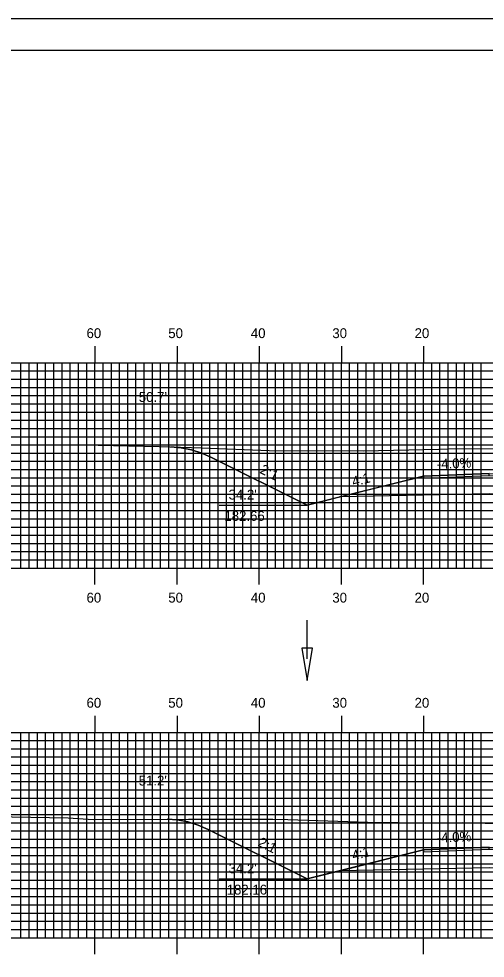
# Model space of a CAD drawing. Extents: x 1797601 to 1797944, y 442591 to 442811.
# Drawn here: x 1797697.2 to 1797753.9, y 442696.2 to 442810.5 of the extents above; entities that cross this region are included whole.
import ezdxf

# ---------------------------------------------------------------- set-up
doc = ezdxf.new("R2010")
doc.units = 0
for name, color, linetype in [('ANNOTATION', 7, 'Continuous'), ('BORDER', 7, 'Continuous'), ('D_Drainage_Ditch_Line', 7, 'Continuous'), ('D_Roadway_Centerline', 7, 'Continuous'), ('D_Roadway_Edge_Shoulder', 7, 'Continuous'), ('D_Roadway_SlopeLines', 7, 'Continuous'), ('D_Roadway_SubGrade', 7, 'Continuous'), ('D_Text_Standard', 7, 'Continuous'), ('H_V ANNOTATION', 7, 'Continuous'), ('MAJOR', 7, 'Continuous'), ('MINOR', 7, 'Continuous'), ('PDRAIN', 7, 'Continuous'), ('PLOT BOUNDARY', 7, 'Continuous'), ('S_Roadway_Centerline', 7, 'Continuous')]:
    doc.layers.add(name, color=color, linetype=linetype)

msp = doc.modelspace()

# ---------------------------------------------------------------- linework, layer by layer
at = {"layer": 'BORDER'}
msp.add_lwpolyline([(1797616.84, 442596.67), (1797936.84, 442596.67), (1797936.84, 442806.67), (1797616.84, 442806.67)], close=True, dxfattribs=at)
at = {"layer": 'D_Drainage_Ditch_Line'}
msp.add_line((1797732.27, 442732.63), (1797732.27, 442737.33), dxfattribs=at)
msp.add_lwpolyline([(1797732.93, 442733.94), (1797731.61, 442733.94), (1797732.27, 442730)], close=True, dxfattribs=at)
at = {"layer": 'D_Roadway_Centerline'}
for points in [[(1797715.7, 442758.42), (1797716.95, 442758.32), (1797718.2, 442758.06), (1797719.45, 442757.66), (1797720.7, 442757.11), (1797732.27, 442751.33), (1797736.27, 442752.33), (1797746.44, 442754.87), (1797754.44, 442755.19), (1797766.44, 442754.95), (1797778.44, 442754.71), (1797786.44, 442754.39), (1797796.62, 442751.85), (1797800.62, 442750.85), (1797811.54, 442756.31), (1797812.79, 442756.85), (1797814.04, 442757.24), (1797815.29, 442757.48), (1797816.54, 442757.55)], [(1797715.24, 442713.09), (1797716.49, 442713.01), (1797717.74, 442712.78), (1797718.99, 442712.39), (1797720.24, 442711.84), (1797732.27, 442705.83), (1797736.27, 442706.83), (1797746.44, 442709.37), (1797754.44, 442709.69), (1797766.44, 442709.45), (1797778.44, 442709.21), (1797786.44, 442708.89), (1797796.62, 442706.35), (1797800.62, 442705.35), (1797811.55, 442710.81), (1797812.8, 442711.35), (1797814.05, 442711.73), (1797815.3, 442711.95), (1797816.55, 442712.01)]]:
    msp.add_lwpolyline(points, dxfattribs=at)
at = {"layer": 'D_Roadway_Edge_Shoulder'}
for points in [[(1797754.44, 442755.19), (1797746.44, 442754.87), (1797746.44, 442754.62), (1797754.44, 442754.94)], [(1797754.44, 442709.69), (1797746.44, 442709.37), (1797746.44, 442709.12), (1797754.44, 442709.44)]]:
    msp.add_lwpolyline(points, close=True, dxfattribs=at)
at = {"layer": 'D_Roadway_SlopeLines'}
for points in [[(1797732.27, 442751.33), (1797720.7, 442757.11), (1797719.45, 442757.66), (1797718.2, 442758.06), (1797716.95, 442758.32), (1797715.7, 442758.42)], [(1797746.44, 442754.87), (1797732.27, 442751.33)], [(1797732.27, 442705.83), (1797720.24, 442711.84), (1797718.99, 442712.39), (1797717.74, 442712.78), (1797716.49, 442713.01), (1797715.24, 442713.09)], [(1797746.44, 442709.37), (1797732.27, 442705.83)]]:
    msp.add_lwpolyline(points, dxfattribs=at)
at = {"layer": 'D_Roadway_SubGrade'}
for points in [[(1797754.44, 442752.69), (1797736.27, 442752.33), (1797746.44, 442754.87), (1797746.44, 442754.62), (1797754.44, 442754.94), (1797766.44, 442754.7), (1797778.44, 442754.46), (1797786.44, 442754.14), (1797786.44, 442754.39), (1797796.62, 442751.85), (1797778.44, 442752.21), (1797766.44, 442752.45)], [(1797754.44, 442707.19), (1797736.27, 442706.83), (1797746.44, 442709.37), (1797746.44, 442709.12), (1797754.44, 442709.44), (1797766.44, 442709.2), (1797778.44, 442708.96), (1797786.44, 442708.64), (1797786.44, 442708.89), (1797796.62, 442706.35), (1797778.44, 442706.71), (1797766.44, 442706.95)]]:
    msp.add_lwpolyline(points, close=True, dxfattribs=at)
at = {"layer": 'MAJOR'}
for p, q in [((1797706.44, 442770.67), (1797706.44, 442768.67)), ((1797716.44, 442770.67), (1797716.44, 442768.67)), ((1797726.44, 442770.67), (1797726.44, 442768.67)), ((1797736.44, 442770.67), (1797736.44, 442768.67)), ((1797746.44, 442770.67), (1797746.44, 442768.67)), ((1797626.44, 442768.67), (1797906.44, 442768.67)), ((1797626.44, 442768.67), (1797906.44, 442768.67)), ((1797706.44, 442743.67), (1797706.44, 442768.67)), ((1797716.44, 442743.67), (1797716.44, 442768.67)), ((1797726.44, 442743.67), (1797726.44, 442768.67)), ((1797736.44, 442743.67), (1797736.44, 442768.67)), ((1797746.44, 442743.67), (1797746.44, 442768.67)), ((1797626.44, 442763.67), (1797906.44, 442763.67)), ((1797626.44, 442758.67), (1797906.44, 442758.67)), ((1797626.44, 442753.67), (1797906.44, 442753.67)), ((1797626.44, 442748.67), (1797906.44, 442748.67)), ((1797626.44, 442743.67), (1797906.44, 442743.67)), ((1797626.44, 442743.67), (1797906.44, 442743.67)), ((1797706.44, 442741.66), (1797706.44, 442743.67)), ((1797716.44, 442741.66), (1797716.44, 442743.67)), ((1797726.44, 442741.66), (1797726.44, 442743.67)), ((1797736.44, 442741.66), (1797736.44, 442743.67)), ((1797746.44, 442741.66), (1797746.44, 442743.67)), ((1797706.44, 442725.67), (1797706.44, 442723.67)), ((1797716.44, 442725.67), (1797716.44, 442723.67)), ((1797726.44, 442725.67), (1797726.44, 442723.67)), ((1797736.44, 442725.67), (1797736.44, 442723.67)), ((1797746.44, 442725.67), (1797746.44, 442723.67)), ((1797626.44, 442723.67), (1797906.44, 442723.67)), ((1797626.44, 442723.67), (1797906.44, 442723.67)), ((1797706.44, 442698.67), (1797706.44, 442723.67)), ((1797716.44, 442698.67), (1797716.44, 442723.67)), ((1797726.44, 442698.67), (1797726.44, 442723.67)), ((1797736.44, 442698.67), (1797736.44, 442723.67)), ((1797746.44, 442698.67), (1797746.44, 442723.67)), ((1797626.44, 442718.67), (1797906.44, 442718.67)), ((1797626.44, 442713.67), (1797906.44, 442713.67)), ((1797626.44, 442708.67), (1797906.44, 442708.67)), ((1797626.44, 442703.67), (1797906.44, 442703.67)), ((1797626.44, 442698.67), (1797906.44, 442698.67)), ((1797626.44, 442698.67), (1797906.44, 442698.67)), ((1797706.44, 442696.66), (1797706.44, 442698.67)), ((1797716.44, 442696.66), (1797716.44, 442698.67)), ((1797726.44, 442696.66), (1797726.44, 442698.67)), ((1797736.44, 442696.66), (1797736.44, 442698.67)), ((1797746.44, 442696.66), (1797746.44, 442698.67))]:
    msp.add_line(p, q, dxfattribs=at)
at = {"layer": 'MINOR'}
for p, q in [((1797626.44, 442767.67), (1797906.44, 442767.67)), ((1797697.44, 442743.67), (1797697.44, 442768.67)), ((1797698.44, 442743.67), (1797698.44, 442768.67)), ((1797699.44, 442743.67), (1797699.44, 442768.67)), ((1797700.44, 442743.67), (1797700.44, 442768.67)), ((1797701.44, 442743.67), (1797701.44, 442768.67)), ((1797702.44, 442743.67), (1797702.44, 442768.67)), ((1797703.44, 442743.67), (1797703.44, 442768.67)), ((1797704.44, 442743.67), (1797704.44, 442768.67)), ((1797705.44, 442743.67), (1797705.44, 442768.67)), ((1797707.44, 442743.67), (1797707.44, 442768.67)), ((1797708.44, 442743.67), (1797708.44, 442768.67)), ((1797709.44, 442743.67), (1797709.44, 442768.67)), ((1797710.44, 442743.67), (1797710.44, 442768.67)), ((1797711.44, 442743.67), (1797711.44, 442768.67)), ((1797712.44, 442743.67), (1797712.44, 442768.67)), ((1797713.44, 442743.67), (1797713.44, 442768.67)), ((1797714.44, 442743.67), (1797714.44, 442768.67)), ((1797715.44, 442743.67), (1797715.44, 442768.67)), ((1797717.44, 442743.67), (1797717.44, 442768.67)), ((1797718.44, 442743.67), (1797718.44, 442768.67)), ((1797719.44, 442743.67), (1797719.44, 442768.67)), ((1797720.44, 442743.67), (1797720.44, 442768.67)), ((1797721.44, 442743.67), (1797721.44, 442768.67)), ((1797722.44, 442743.67), (1797722.44, 442768.67)), ((1797723.44, 442743.67), (1797723.44, 442768.67)), ((1797724.44, 442743.67), (1797724.44, 442768.67)), ((1797725.44, 442743.67), (1797725.44, 442768.67)), ((1797727.44, 442743.67), (1797727.44, 442768.67)), ((1797728.44, 442743.67), (1797728.44, 442768.67)), ((1797729.44, 442743.67), (1797729.44, 442768.67)), ((1797730.44, 442743.67), (1797730.44, 442768.67)), ((1797731.44, 442743.67), (1797731.44, 442768.67)), ((1797732.44, 442743.67), (1797732.44, 442768.67)), ((1797733.44, 442743.67), (1797733.44, 442768.67)), ((1797734.44, 442743.67), (1797734.44, 442768.67)), ((1797735.44, 442743.67), (1797735.44, 442768.67)), ((1797737.44, 442743.67), (1797737.44, 442768.67)), ((1797738.44, 442743.67), (1797738.44, 442768.67)), ((1797739.44, 442743.67), (1797739.44, 442768.67)), ((1797740.44, 442743.67), (1797740.44, 442768.67)), ((1797741.44, 442743.67), (1797741.44, 442768.67)), ((1797742.44, 442743.67), (1797742.44, 442768.67)), ((1797743.44, 442743.67), (1797743.44, 442768.67)), ((1797744.44, 442743.67), (1797744.44, 442768.67)), ((1797745.44, 442743.67), (1797745.44, 442768.67)), ((1797747.44, 442743.67), (1797747.44, 442768.67)), ((1797748.44, 442743.67), (1797748.44, 442768.67)), ((1797749.44, 442743.67), (1797749.44, 442768.67)), ((1797750.44, 442743.67), (1797750.44, 442768.67)), ((1797751.44, 442743.67), (1797751.44, 442768.67)), ((1797752.44, 442743.67), (1797752.44, 442768.67)), ((1797753.44, 442743.67), (1797753.44, 442768.67)), ((1797626.44, 442766.67), (1797906.44, 442766.67)), ((1797626.44, 442765.67), (1797906.44, 442765.67)), ((1797626.44, 442764.67), (1797906.44, 442764.67)), ((1797626.44, 442762.67), (1797906.44, 442762.67)), ((1797626.44, 442761.67), (1797906.44, 442761.67)), ((1797626.44, 442760.67), (1797906.44, 442760.67)), ((1797626.44, 442759.67), (1797906.44, 442759.67)), ((1797626.44, 442757.67), (1797906.44, 442757.67)), ((1797626.44, 442756.67), (1797906.44, 442756.67)), ((1797626.44, 442755.67), (1797906.44, 442755.67)), ((1797626.44, 442754.67), (1797906.44, 442754.67)), ((1797626.44, 442752.67), (1797906.44, 442752.67)), ((1797626.44, 442751.67), (1797906.44, 442751.67)), ((1797626.44, 442750.67), (1797906.44, 442750.67)), ((1797626.44, 442749.67), (1797906.44, 442749.67)), ((1797626.44, 442747.67), (1797906.44, 442747.67)), ((1797626.44, 442746.67), (1797906.44, 442746.67)), ((1797626.44, 442745.67), (1797906.44, 442745.67)), ((1797626.44, 442744.67), (1797906.44, 442744.67)), ((1797697.44, 442698.67), (1797697.44, 442723.67)), ((1797698.44, 442698.67), (1797698.44, 442723.67)), ((1797699.44, 442698.67), (1797699.44, 442723.67)), ((1797700.44, 442698.67), (1797700.44, 442723.67)), ((1797701.44, 442698.67), (1797701.44, 442723.67)), ((1797702.44, 442698.67), (1797702.44, 442723.67)), ((1797703.44, 442698.67), (1797703.44, 442723.67)), ((1797704.44, 442698.67), (1797704.44, 442723.67)), ((1797705.44, 442698.67), (1797705.44, 442723.67)), ((1797707.44, 442698.67), (1797707.44, 442723.67)), ((1797708.44, 442698.67), (1797708.44, 442723.67)), ((1797709.44, 442698.67), (1797709.44, 442723.67)), ((1797710.44, 442698.67), (1797710.44, 442723.67)), ((1797711.44, 442698.67), (1797711.44, 442723.67)), ((1797712.44, 442698.67), (1797712.44, 442723.67)), ((1797713.44, 442698.67), (1797713.44, 442723.67)), ((1797714.44, 442698.67), (1797714.44, 442723.67)), ((1797715.44, 442698.67), (1797715.44, 442723.67)), ((1797717.44, 442698.67), (1797717.44, 442723.67)), ((1797718.44, 442698.67), (1797718.44, 442723.67)), ((1797719.44, 442698.67), (1797719.44, 442723.67)), ((1797720.44, 442698.67), (1797720.44, 442723.67)), ((1797721.44, 442698.67), (1797721.44, 442723.67)), ((1797722.44, 442698.67), (1797722.44, 442723.67)), ((1797723.44, 442698.67), (1797723.44, 442723.67)), ((1797724.44, 442698.67), (1797724.44, 442723.67)), ((1797725.44, 442698.67), (1797725.44, 442723.67)), ((1797727.44, 442698.67), (1797727.44, 442723.67)), ((1797728.44, 442698.67), (1797728.44, 442723.67)), ((1797729.44, 442698.67), (1797729.44, 442723.67)), ((1797730.44, 442698.67), (1797730.44, 442723.67)), ((1797731.44, 442698.67), (1797731.44, 442723.67)), ((1797732.44, 442698.67), (1797732.44, 442723.67)), ((1797733.44, 442698.67), (1797733.44, 442723.67)), ((1797734.44, 442698.67), (1797734.44, 442723.67)), ((1797735.44, 442698.67), (1797735.44, 442723.67)), ((1797737.44, 442698.67), (1797737.44, 442723.67)), ((1797738.44, 442698.67), (1797738.44, 442723.67)), ((1797739.44, 442698.67), (1797739.44, 442723.67)), ((1797740.44, 442698.67), (1797740.44, 442723.67)), ((1797741.44, 442698.67), (1797741.44, 442723.67)), ((1797742.44, 442698.67), (1797742.44, 442723.67)), ((1797743.44, 442698.67), (1797743.44, 442723.67)), ((1797744.44, 442698.67), (1797744.44, 442723.67)), ((1797745.44, 442698.67), (1797745.44, 442723.67)), ((1797747.44, 442698.67), (1797747.44, 442723.67)), ((1797748.44, 442698.67), (1797748.44, 442723.67)), ((1797749.44, 442698.67), (1797749.44, 442723.67)), ((1797750.44, 442698.67), (1797750.44, 442723.67)), ((1797751.44, 442698.67), (1797751.44, 442723.67)), ((1797752.44, 442698.67), (1797752.44, 442723.67)), ((1797753.44, 442698.67), (1797753.44, 442723.67)), ((1797626.44, 442722.67), (1797906.44, 442722.67)), ((1797626.44, 442721.67), (1797906.44, 442721.67)), ((1797626.44, 442720.67), (1797906.44, 442720.67)), ((1797626.44, 442719.67), (1797906.44, 442719.67)), ((1797626.44, 442717.67), (1797906.44, 442717.67)), ((1797626.44, 442716.67), (1797906.44, 442716.67)), ((1797626.44, 442715.67), (1797906.44, 442715.67)), ((1797626.44, 442714.67), (1797906.44, 442714.67)), ((1797626.44, 442712.67), (1797906.44, 442712.67)), ((1797626.44, 442711.67), (1797906.44, 442711.67)), ((1797626.44, 442710.67), (1797906.44, 442710.67)), ((1797626.44, 442709.67), (1797906.44, 442709.67)), ((1797626.44, 442707.67), (1797906.44, 442707.67)), ((1797626.44, 442706.67), (1797906.44, 442706.67)), ((1797626.44, 442705.67), (1797906.44, 442705.67)), ((1797626.44, 442704.67), (1797906.44, 442704.67)), ((1797626.44, 442702.67), (1797906.44, 442702.67)), ((1797626.44, 442701.67), (1797906.44, 442701.67)), ((1797626.44, 442700.67), (1797906.44, 442700.67)), ((1797626.44, 442699.67), (1797906.44, 442699.67))]:
    msp.add_line(p, q, dxfattribs=at)
at = {"layer": 'PDRAIN'}
for p, q in [((1797721.55, 442751.33), (1797732.27, 442751.33)), ((1797721.55, 442705.83), (1797732.27, 442705.83))]:
    msp.add_line(p, q, dxfattribs=at)
at = {"layer": 'PLOT BOUNDARY'}
msp.add_lwpolyline([(1797600.66, 442590.55), (1797940.66, 442590.55), (1797940.66, 442810.55), (1797600.66, 442810.55)], close=True, dxfattribs=at)
at = {"layer": 'S_Roadway_Centerline'}
for points in [[(1797687.49, 442758.66), (1797706.84, 442758.62), (1797714.27, 442758.46), (1797719.49, 442758.33), (1797727.64, 442757.98), (1797739.12, 442757.93), (1797748.29, 442758.14), (1797750.47, 442758.21), (1797759.46, 442758.19), (1797770.12, 442757.67), (1797776.56, 442757.62), (1797791.48, 442757.23), (1797792.06, 442757.23), (1797792.74, 442757.24), (1797803.41, 442757.41), (1797812.83, 442757.56), (1797815.62, 442757.56), (1797819.14, 442757.53), (1797826.47, 442757.28)], [(1797684.96, 442713.57), (1797703.19, 442713.25), (1797706.24, 442713.08), (1797717.85, 442713.09), (1797726.83, 442713.11), (1797728.09, 442713.12), (1797729.92, 442713.04), (1797739.67, 442712.73), (1797747.14, 442712.67), (1797751.16, 442712.71), (1797756.7, 442712.55), (1797763.19, 442712.49), (1797768.08, 442712.38), (1797782.33, 442712.24), (1797788.49, 442712.18), (1797807.51, 442712.17), (1797808.37, 442712.16), (1797809.09, 442712.17), (1797821.72, 442711.89), (1797830.65, 442711.71)]]:
    msp.add_lwpolyline(points, dxfattribs=at)

# ---------------------------------------------------------------- texts
at = {"layer": 'ANNOTATION'}
for s, rotation, p in [('2:1', 333.4349, (1797726.42, 442755.29)), ('-4.0%', 2.2906, (1797748.08, 442755.74)), ('4:1', 14.0362, (1797737.89, 442753.59)), ('-4.0%', 2.2906, (1797748.08, 442710.24)), ('2:1', 333.4349, (1797726.19, 442709.9)), ('4:1', 14.0362, (1797737.89, 442708.09))]:
    msp.add_text(s, height=1.2, rotation=rotation, dxfattribs=at).set_placement(p)
for s, p in [("34.2'", (1797722.71, 442752.02)), ('182.66', (1797722.2, 442749.42)), ("34.2'", (1797722.71, 442706.52)), ('182.16', (1797722.48, 442703.92))]:
    msp.add_text(s, height=1.2, dxfattribs=at).set_placement(p)
at = {"layer": 'D_Text_Standard'}
for s, p in [("50.7'", (1797711.78, 442763.9)), ("51.2'", (1797711.77, 442717.2))]:
    msp.add_text(s, height=1.2, dxfattribs=at).set_placement(p)
at = {"layer": 'H_V ANNOTATION'}
for s, p in [('60', (1797705.42, 442771.67)), ('50', (1797715.37, 442771.67)), ('40', (1797725.42, 442771.67)), ('30', (1797735.34, 442771.67)), ('20', (1797745.35, 442771.67)), ('60', (1797705.42, 442739.47)), ('50', (1797715.37, 442739.47)), ('40', (1797725.42, 442739.47)), ('30', (1797735.34, 442739.47)), ('20', (1797745.35, 442739.47)), ('60', (1797705.42, 442726.67)), ('50', (1797715.37, 442726.67)), ('40', (1797725.42, 442726.67)), ('30', (1797735.34, 442726.67)), ('20', (1797745.35, 442726.67))]:
    msp.add_text(s, height=1.2, dxfattribs=at).set_placement(p)

doc.saveas('drawing.dxf')
